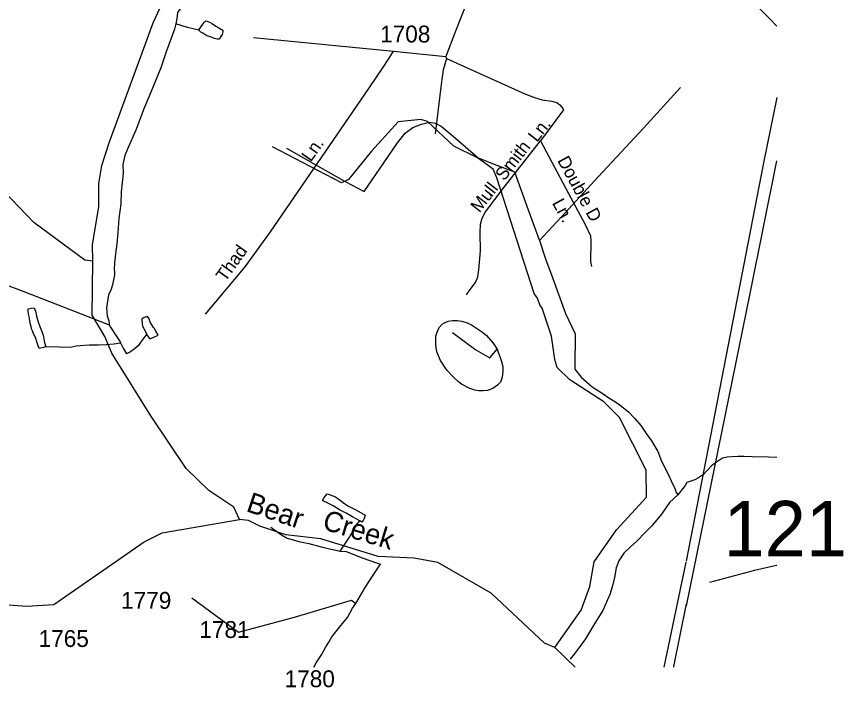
# Model space of a CAD drawing. Extents: x 2315291 to 2336543, y 597177 to 615230.
# Drawn here: x 2330419 to 2336543, y 597379 to 602347 of the extents above; entities that cross this region are included whole.
import ezdxf

# ---------------------------------------------------------------- set-up
doc = ezdxf.new("R2010")
doc.units = 0
for name, color, linetype in [('Exist Hydrographic Creek Single Shore', 7, 'Continuous'), ('Exist Hydrographic Creek Single Shore Label', 7, 'Continuous'), ('Exist Hydrographic Misc Water Feature', 7, 'Continuous'), ('Exist Road Non-System Type 51', 7, 'Continuous'), ('Exist Road Non-System Type 51 Label', 7, 'Continuous'), ('Exist Road Primary US Attributed', 7, 'Continuous'), ('Exist Road Secondary Structure Standard Bridge Number Label', 7, 'Continuous'), ('Exist Road Secondary Type 51 Attributed', 7, 'Continuous'), ('Exist Road Secondary Type 51 Number Label', 7, 'Continuous'), ('Exist Utilities Electrical Transmission Line', 7, 'Continuous')]:
    doc.layers.add(name, color=color, linetype=linetype)

msp = doc.modelspace()

# ---------------------------------------------------------------- linework, layer by layer
at = {"layer": 'Exist Hydrographic Creek Single Shore'}
msp.add_line((2334555, 597529.5), (2334404.6, 597673.6), dxfattribs=at)
for points in [[(2330983.5, 600534.7), (2330925.5, 600542.2), (2330547.5, 600822.3), (2330210.4, 601169.6), (2329763.4, 601712.7), (2329619.5, 601920.2), (2329459.3, 602110.6), (2329232.3, 602275.3), (2328880.5, 602461.4), (2328496.4, 602590.1), (2328144.3, 602763), (2328109.5, 602896.1), (2328072.4, 603219.6), (2327695.5, 603483.2), (2327485.3, 603638.8), (2327451.5, 603712.9), (2327081.3, 604026.1)], [(2330983.5, 600534.7), (2330982.5, 600659.3), (2331029.4, 600936.9), (2331027.4, 601110.8), (2331050.5, 601243), (2331107.5, 601419.2), (2331430.5, 602298.7), (2331553.5, 602566.1)], [(2332070.5, 598622.7), (2332027.4, 598712.9), (2331842.4, 598836.8), (2331674.5, 599000.6), (2331412.5, 599390.3), (2331124.4, 599854.5), (2331072.5, 599977.1), (2330979.4, 600134.2), (2330983.5, 600534.7)], [(2329786.4, 598031.6), (2330494.4, 597981.5), (2330694.4, 597992.9), (2331363.4, 598456.3), (2331496.5, 598524.1), (2332070.5, 598622.7)], [(2334404.6, 597673.6), (2334328.5, 597706.6), (2333933.6, 598077.9), (2333539.5, 598304.8), (2333364.6, 598337.1), (2333097.6, 598349.3), (2332671.5, 598479.7), (2332412.5, 598508.6), (2332220.6, 598573.1), (2332136.5, 598615.6), (2332070.5, 598622.7)]]:
    msp.add_lwpolyline(points, dxfattribs=at)
at = {"layer": 'Exist Hydrographic Misc Water Feature'}
for points in [[(2331695.2, 602507.8), (2331654.2, 602437.3), (2331610.5, 602376.9), (2331605.4, 602332.7), (2331597.4, 602292.9)], [(2331597.4, 602292.9), (2331588.2, 602252.6), (2331527.9, 602084), (2331487.3, 601965.6), (2331425, 601815.3), (2331362.4, 601662.4), (2331302.1, 601504), (2331245.7, 601377.4), (2331220.1, 601317.2), (2331207, 601251.1), (2331207.8, 601187.3), (2331193.3, 601049.1), (2331190.2, 600959.2), (2331177.5, 600851.2), (2331168.6, 600747.1), (2331161.5, 600663), (2331152.4, 600588.9), (2331144.9, 600522.8), (2331141.2, 600473), (2331143.8, 600454.8)], [(2331770.1, 602246.7), (2331683.9, 602265.8), (2331597.4, 602292.9)], [(2331770.1, 602246.7), (2331776, 602256.8), (2331797.7, 602290.8), (2331811.5, 602304.9), (2331820.9, 602315.3), (2331831.2, 602313.3), (2331853.5, 602301.5), (2331869.7, 602291.7), (2331893.9, 602275.9), (2331917.9, 602262.2), (2331936, 602250.5), (2331946, 602244.6), (2331946.2, 602232.8), (2331940.7, 602214.5), (2331926.7, 602190.3), (2331920.8, 602180.2), (2331912.8, 602180.2), (2331904.8, 602180.2), (2331884.5, 602184), (2331854.5, 602195.5), (2331828.7, 602203.4), (2331798.4, 602223), (2331784.4, 602230.7), (2331770.1, 602246.7)], [(2335336.3, 601821.3), (2335062.4, 601520.2), (2334728.4, 601162.9), (2334453.4, 600862), (2334291.6, 600688.4)], [(2334404.6, 597673.6), (2334601.4, 597950.6), (2334665.6, 598127.2), (2334697.6, 598308.9), (2334861.4, 598545.2), (2335083.5, 598787.2), (2335081.5, 598987.4), (2334885.4, 599376.5), (2334767.5, 599493.2), (2334516.5, 599656.9), (2334423.4, 599748.4), (2334406.4, 599806.8), (2334379.6, 599979.6), (2334310.5, 600186.8), (2334293.4, 600212.4), (2334276.4, 600261), (2334251.6, 600296), (2333975.4, 601151.2), (2333949.6, 601215.8), (2333832.5, 601299.7), (2333656.5, 601387.7), (2333462.6, 601570.2), (2333412.5, 601584.6), (2333246.4, 601568.1), (2333048.6, 601350), (2332876.5, 601139.6), (2332826.5, 601114.6), (2332315.5, 601382.7)], [(2332417, 601371.9), (2332630.1, 601250.3), (2332853.8, 601125), (2332992.2, 601050.2), (2333138.2, 601263.9), (2333240.3, 601410.7), (2333297.5, 601483.6), (2333354.9, 601524), (2333418.7, 601550.5), (2333476.5, 601563.3), (2333520.4, 601558), (2333562.6, 601534.1), (2333669.5, 601445.5), (2333837.2, 601301.4), (2333955.7, 601252.8), (2334106.2, 601196.5), (2334198.9, 600941.3), (2334289.5, 600692.4), (2334291.6, 600688.4)], [(2334291.6, 600688.4), (2334336.9, 600553.1), (2334390.2, 600405.9)], [(2330033.9, 600477), (2330473.5, 600309.9), (2330897, 600146.4), (2331105.7, 600064.7)], [(2331143.8, 600454.8), (2331143.8, 600432.9), (2331134.2, 600384.9), (2331128.7, 600358.9), (2331119, 600326.7), (2331099.5, 600286.6), (2331093.8, 600254.3), (2331086.2, 600188.5), (2331091.1, 600130.6), (2331101.2, 600094.6), (2331103.6, 600072.8), (2331105.7, 600064.7)], [(2334390.2, 600405.9), (2334485.2, 600148.7), (2334556.5, 599997.7), (2334553.6, 599747.9), (2334553.4, 599735.8), (2334600.4, 599676.4), (2334682.8, 599605.2), (2334755.4, 599558.2), (2334811.8, 599518.9), (2334855.9, 599493.2), (2334892, 599467.5), (2334950.8, 599420.1), (2334995.3, 599372.9), (2335041.7, 599317.2), (2335082.3, 599259.6), (2335121, 599204.3), (2335167.8, 599126.7), (2335196.5, 599055), (2335245.5, 598957.7), (2335266, 598908), (2335294.5, 598852.1), (2335305, 598822.2), (2335317.3, 598804.5)], [(2330635.5, 599903.9), (2330618.1, 599895.6), (2330585.9, 599889), (2330577.5, 599915.1), (2330569.5, 599939), (2330559.2, 599968.9), (2330547.1, 599992.6), (2330536.5, 600018.6), (2330530.7, 600034.5), (2330526.4, 600052.5), (2330521.9, 600066.6), (2330518, 600088.3), (2330513.9, 600112.4), (2330509.4, 600132.1), (2330505.1, 600162), (2330505.1, 600182.3), (2330526.4, 600188.4), (2330549, 600190.7), (2330559, 600164.8), (2330567.6, 600129.1), (2330579.9, 600085), (2330592, 600051.2), (2330606.6, 600013.3), (2330615, 599987.3), (2330621.2, 599957.6), (2330625.7, 599933.4), (2330635.5, 599903.9)], [(2331105.7, 600064.7), (2331115.7, 600047), (2331156.8, 599981.2), (2331185.3, 599937.6), (2331189.4, 599931.7)], [(2331382.5, 599991.8), (2331406.5, 599959.8), (2331436.7, 599972.3), (2331468.2, 599986.7), (2331450.4, 600016.5), (2331437.7, 600040.3), (2331434.2, 600044.1), (2331409.4, 600083.9), (2331401.4, 600107.8), (2331389.1, 600125.5), (2331363.4, 600117.2), (2331347.5, 600105.4), (2331349.7, 600073.4), (2331352, 600053.2), (2331374.1, 600015.4), (2331380.7, 599995.8), (2331382.5, 599991.8)], [(2333978.3, 599883.6), (2333986.5, 599861.6), (2333999, 599829.7), (2334011.5, 599791.8), (2334019.5, 599756.1), (2334020.1, 599721.9), (2334016.4, 599676.3), (2334003.3, 599640.2), (2333981.3, 599615.9), (2333945.3, 599591.3), (2333907.7, 599577.1), (2333875.7, 599574.5), (2333841.7, 599574.4), (2333813.8, 599579.8), (2333775.5, 599591.7), (2333713.3, 599624.9), (2333692.8, 599642.6), (2333654.7, 599676.4), (2333608.2, 599725.5), (2333589.9, 599751.4), (2333573.9, 599777.3), (2333559.6, 599798.9), (2333532.7, 599864.6), (2333524.1, 599912.6), (2333524.3, 599936.5), (2333523.7, 599978.8), (2333533.3, 600008.5), (2333548.7, 600043.1), (2333570.4, 600069), (2333588.3, 600079.3), (2333616.4, 600091.7), (2333648.5, 600095.8), (2333682.2, 600096.4), (2333716, 600090.5), (2333756.2, 600079.2), (2333788.4, 600063.4), (2333826.5, 600039.8), (2333871, 600008.4), (2333899.5, 599984.7), (2333949.8, 599929.2), (2333978.3, 599883.6)], [(2333647.1, 600006), (2333820.4, 599879.8), (2333922.9, 599818.9), (2333978.3, 599883.6)], [(2331382.5, 599991.8), (2331355, 599957.4), (2331319.4, 599908.9), (2331289.4, 599882.6), (2331264, 599864.5), (2331234.1, 599848.3)], [(2330635.5, 599903.9), (2330735.8, 599900.6), (2330816, 599899.5), (2330859.8, 599908.3), (2330891.2, 599910.4), (2330957.4, 599915.1), (2331025.5, 599915.8), (2331083.3, 599918.4), (2331138.9, 599923), (2331189.4, 599931.7)], [(2331189.4, 599931.7), (2331209.5, 599891.8), (2331234.1, 599848.3)], [(2336050.3, 599082.2), (2335987.8, 599082.8), (2335865.8, 599087), (2335806.1, 599088.3), (2335760.2, 599087.9), (2335715.9, 599085.2), (2335682.3, 599085), (2335648.2, 599076.8), (2335602.7, 599045.9), (2335565.2, 599019.5), (2335529.3, 598981.1), (2335507.6, 598955.1), (2335470, 598930.4), (2335442.5, 598916.3), (2335382.1, 598895.4), (2335370.6, 598875.2)], [(2335370.6, 598875.2), (2335362.6, 598865.1), (2335317.3, 598804.5)], [(2332960.2, 598613.3), (2332908.1, 598642.6), (2332860.1, 598670.2), (2332809.5, 598693.5), (2332763.5, 598723.2), (2332719.3, 598746.5), (2332685, 598762.2), (2332696.7, 598786.4), (2332718.4, 598812.7), (2332742.6, 598805), (2332780.8, 598789.1), (2332808.4, 598771.6), (2332824.9, 598757.8), (2332841.3, 598746), (2332873.2, 598724.1), (2332935.8, 598690.8), (2333000.2, 598653.6), (2332994.4, 598629.7), (2332986.4, 598615.4), (2332976.4, 598603.6), (2332960.2, 598613.3)], [(2335317.3, 598804.5), (2335255.5, 598747.7), (2335194.8, 598661.1), (2335123.7, 598576.6), (2335074.1, 598526), (2335015.2, 598465.2), (2334965.8, 598419), (2334916, 598372.2), (2334880.7, 598315.9), (2334859.2, 598264), (2334848.1, 598193.8), (2334832.5, 598131.7), (2334813.4, 598067.3), (2334761, 597949), (2334701.9, 597854.1), (2334633, 597739.5), (2334585.8, 597675.3), (2334548.5, 597624.9), (2334518.6, 597588.5)], [(2332815.2, 598387.8), (2332883.7, 598492.6), (2332932.9, 598578.9), (2332960.2, 598613.3)], [(2332301.4, 598566.1), (2332321.7, 598550.4), (2332381.9, 598508.9), (2332424, 598483.5), (2332434.2, 598481.6), (2332510.3, 598460.4), (2332584.5, 598445.2), (2332674.8, 598420.2), (2332748.8, 598403), (2332807, 598389.8), (2332815.2, 598387.8)], [(2332815.2, 598387.8), (2332860.9, 598384.5), (2332977.6, 598339.4), (2333083.8, 598300.7), (2333113.6, 598291)], [(2332931.1, 598001.3), (2332999.8, 598117.9), (2333059, 598210.4), (2333113.6, 598291)], [(2331717.4, 598042.4), (2332061.9, 597788.2), (2332478.3, 597898.7), (2332900.5, 598024.9), (2332931.1, 598001.3)], [(2332620.9, 597529.5), (2332638.1, 597560.4), (2332677.4, 597620.6), (2332706.7, 597674.9), (2332732.2, 597715.3), (2332753.9, 597753.4), (2332820.8, 597838.3), (2332870.4, 597896.5), (2332907.7, 597965.1), (2332931.1, 598001.3)]]:
    msp.add_lwpolyline(points, dxfattribs=at)
at = {"layer": 'Exist Road Non-System Type 51'}
for p, q in [((2333670.6, 602237.2), (2333598.4, 602049.9)), ((2332173.1, 602190.6), (2333210.7, 602089.8)), ((2333210.7, 602089.8), (2333598.4, 602049.9)), ((2333598.4, 602049.9), (2333602.2, 602035.9))]:
    msp.add_line(p, q, dxfattribs=at)
for points in [[(2331817.7, 600142.6), (2332112.3, 600492.5), (2332300.4, 600752.1), (2332910.4, 601641), (2333034, 601821.7), (2333085.3, 601897.8), (2333127.1, 601960.5), (2333178.4, 602038.5), (2333210.7, 602089.8)], [(2333602.2, 602035.9), (2333577.5, 601951), (2333564.2, 601842.6), (2333518.6, 601477.5)], [(2333602.2, 602035.9), (2334183.7, 601773.5), (2334254.6, 601746.9), (2334311.6, 601730.4), (2334383.9, 601719), (2334419.3, 601708.9), (2334442.1, 601692.4), (2334461.1, 601667), (2334468.7, 601655.6), (2334300.2, 601427.4)], [(2333752.3, 600285.2), (2333778.9, 600325.2), (2333818.8, 600376.5), (2333835.9, 600420.3), (2333843.5, 600471.6), (2333854.3, 600612.2), (2333853, 600745.4), (2333854.9, 600810.1), (2333866.3, 600853.8), (2333892.9, 600901.3), (2334029.8, 601082), (2334300.2, 601427.4)], [(2334300.2, 601427.4), (2334506.7, 601035.4), (2334628.4, 600812), (2334670.2, 600722.6), (2334672.1, 600684.6), (2334668.8, 600531), (2334675.9, 600496.3)], [(2336050.3, 598281.7), (2336047.3, 598281), (2335884.9, 598243.7), (2335551.4, 598155.9)]]:
    msp.add_lwpolyline(points, dxfattribs=at)
at = {"layer": 'Exist Road Primary US Attributed'}
msp.add_arc((2330534.8, 596996.6), 7633.7, 43.73712, 62.20482, dxfattribs=at)
at = {"layer": 'Exist Road Secondary Type 51 Attributed'}
msp.add_lwpolyline([(2334850.7, 605199.8), (2334362.3, 603993.3), (2334050.7, 603230.7), (2333834, 602652.7), (2333670.6, 602237.2)], dxfattribs=at)
at = {"layer": 'Exist Utilities Electrical Transmission Line'}
for points in [[(2336050.3, 601748.2), (2335952, 601264.2), (2335377.6, 598312.7)], [(2335379.6, 597982.8), (2335851.5, 600295.5), (2336050.3, 601277.9)], [(2335376.3, 598307.6), (2335213.9, 597529.5)], [(2335286, 597529.5), (2335286.7, 597533.2), (2335379.7, 597997.9)]]:
    msp.add_lwpolyline(points, dxfattribs=at)

# ---------------------------------------------------------------- texts
at = {"layer": 'Exist Hydrographic Creek Single Shore Label'}
for s, rotation, p in [('Bear', 341.44129, (2332112.1, 598685.6)), ('Creek', 342.98256, (2332675.8, 598553.8))]:
    msp.add_text(s, height=150, rotation=rotation, dxfattribs=at).set_placement(p)
at = {"layer": 'Exist Road Non-System Type 51 Label'}
for s, rotation, p in [('Ln.', 52.05374, (2334273.4, 601410.5)), ('Smith', 52.05374, (2334030.7, 601124.3)), ('Ln.', 54.44986, (2332598, 601265)), ('Double D', 298.63628, (2334421.3, 601281.3)), ('Mull', 52.05374, (2333847.4, 600888.4)), ('Ln.', 298.63628, (2334382.7, 600966.3)), ('Thad', 54.44986, (2331965.1, 600376.6))]:
    msp.add_text(s, height=95, rotation=rotation, dxfattribs=at).set_placement(p)
at = {"layer": 'Exist Road Secondary Structure Standard Bridge Number Label'}
msp.add_text('121', height=410.1, dxfattribs=at).set_placement((2335654.9, 598349.8))
at = {"layer": 'Exist Road Secondary Type 51 Number Label'}
for s, p in [('1708', (2333111.6, 602154.4)), ('1779', (2331193.2, 597961)), ('1781', (2331772.7, 597745.2)), ('1765', (2330582.6, 597678.5)), ('1780', (2332404.3, 597380.5))]:
    msp.add_text(s, height=125, dxfattribs=at).set_placement(p)

doc.saveas('drawing.dxf')
